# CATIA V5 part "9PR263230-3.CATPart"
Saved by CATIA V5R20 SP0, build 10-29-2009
Part number: 9PR263230-3
Revision: ANY
Definition: UNKNOWN
Nomenclature: 9PR263230-3
Source: Unknown
Bounding box of the stored display mesh (mm): x 0 to 30, y -8 to 8, z -8 to 8
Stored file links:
  C:\Users\Utente\Desktop\IO LAVORO\3D X SITO CF\CUMSA\3D files PR.233230\PR 263230\9PR263230-3.CATPart
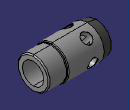
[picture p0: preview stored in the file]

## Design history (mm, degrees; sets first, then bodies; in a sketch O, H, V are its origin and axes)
Body1 "Chaflán3" (main body)
  Solid1: solid without history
